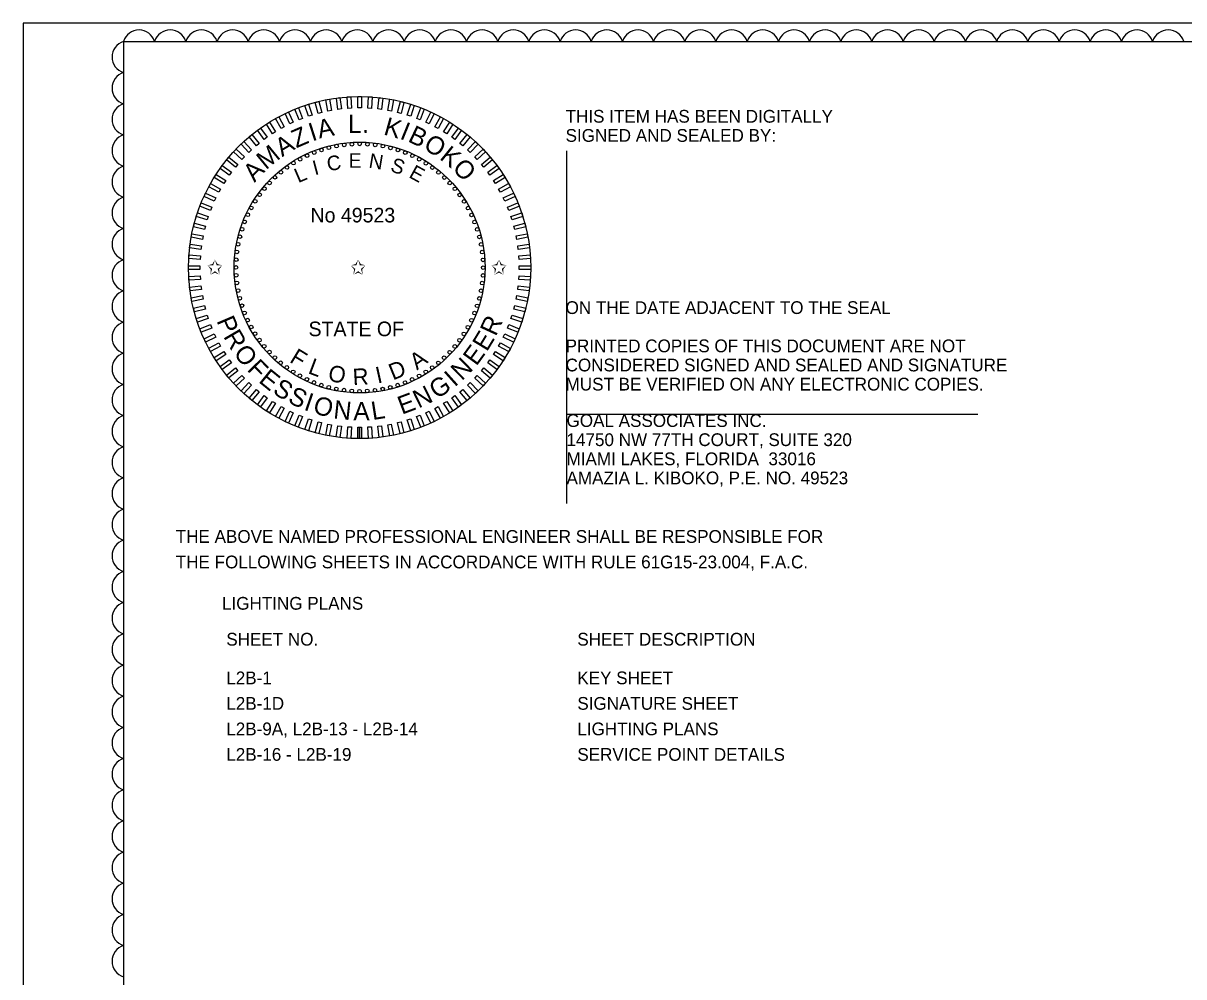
# Model space of a CAD drawing. Extents: x -816.9 to -790.1, y -2199.5 to -2184.5.
# Drawn here: x -811.34 to -804.97, y -2194.13 to -2188.9 of the extents above; entities that cross this region are included whole.
import ezdxf

# ---------------------------------------------------------------- set-up
doc = ezdxf.new("R2010")
doc.units = 0
for name, color, linetype in [('Cloud_dp', 7, 'Continuous'), ('Logo_dp', 7, 'Continuous'), ('NonPlottingEle_dp', 7, 'Continuous'), ('PlotBorder_dp', 7, 'Continuous'), ('ScratchEle_dp', 7, 'Continuous'), ('SheetBorder_dp', 7, 'Continuous'), ('TextMisc', 7, 'Continuous'), ('TextNotes', 7, 'Continuous')]:
    doc.layers.add(name, color=color, linetype=linetype)

msp = doc.modelspace()

# ---------------------------------------------------------------- linework, layer by layer
at = {"layer": 'Cloud_dp'}
for centre, start, end in [((-810.7002, -2189.0276), 17.5, 162.5), ((-810.5291, -2189.0276), 17.5, 162.5), ((-810.358, -2189.0276), 17.5, 162.5), ((-810.1868, -2189.0276), 17.5, 162.5), ((-810.0157, -2189.0276), 17.5, 162.5), ((-809.8446, -2189.0276), 17.5, 162.5), ((-809.6735, -2189.0276), 17.5, 162.5), ((-809.5024, -2189.0276), 17.5, 162.5), ((-809.3312, -2189.0276), 17.5, 162.5), ((-809.1601, -2189.0276), 17.5, 162.5), ((-808.989, -2189.0276), 17.5, 162.5), ((-808.8179, -2189.0276), 17.5, 162.5), ((-808.6467, -2189.0276), 17.5, 162.5), ((-808.4756, -2189.0276), 17.5, 162.5), ((-808.3045, -2189.0276), 17.5, 162.5), ((-808.1334, -2189.0276), 17.5, 162.5), ((-807.9622, -2189.0276), 17.5, 162.5), ((-807.7911, -2189.0276), 17.5, 162.5), ((-807.62, -2189.0276), 17.5, 162.5), ((-807.4489, -2189.0276), 17.5, 162.5), ((-807.2778, -2189.0276), 17.5, 162.5), ((-807.1066, -2189.0276), 17.5, 162.5), ((-806.9355, -2189.0276), 17.5, 162.5), ((-806.7644, -2189.0276), 17.5, 162.5), ((-806.5933, -2189.0276), 17.5, 162.5), ((-806.4221, -2189.0276), 17.5, 162.5), ((-806.251, -2189.0276), 17.5, 162.5), ((-806.0799, -2189.0276), 17.5, 162.5), ((-805.9088, -2189.0276), 17.5, 162.5), ((-805.7377, -2189.0276), 17.5, 162.5), ((-805.5665, -2189.0276), 17.5, 162.5), ((-805.3954, -2189.0276), 17.5, 162.5), ((-805.2243, -2189.0276), 17.5, 162.5), ((-805.0532, -2189.0276), 17.5, 162.5), ((-810.7588, -2189.0862), 107.5, 252.5), ((-810.7588, -2189.2573), 107.5, 252.5), ((-810.7588, -2189.4284), 107.5, 252.5), ((-810.7588, -2189.5996), 107.5, 252.5), ((-810.7588, -2189.7707), 107.5, 252.5), ((-810.7588, -2189.9418), 107.5, 252.5), ((-810.7588, -2190.1129), 107.5, 252.5), ((-810.7588, -2190.2841), 107.5, 252.5), ((-810.7588, -2190.4552), 107.5, 252.5), ((-810.7588, -2190.6263), 107.5, 252.5), ((-810.7588, -2190.7974), 107.5, 252.5), ((-810.7588, -2190.9685), 107.5, 252.5), ((-810.7588, -2191.1397), 107.5, 252.5), ((-810.7588, -2191.3108), 107.5, 252.5), ((-810.7588, -2191.4819), 107.5, 252.5), ((-810.7588, -2191.653), 107.5, 252.5), ((-810.7588, -2191.8242), 107.5, 252.5), ((-810.7588, -2191.9953), 107.5, 252.5), ((-810.7588, -2192.1664), 107.5, 252.5), ((-810.7588, -2192.3375), 107.5, 252.5), ((-810.7588, -2192.5087), 107.5, 252.5), ((-810.7588, -2192.6798), 107.5, 252.5), ((-810.7588, -2192.8509), 107.5, 252.5), ((-810.7588, -2193.022), 107.5, 252.5), ((-810.7588, -2193.1931), 107.5, 252.5), ((-810.7588, -2193.3643), 107.5, 252.5), ((-810.7588, -2193.5354), 107.5, 252.5), ((-810.7588, -2193.7065), 107.5, 252.5), ((-810.7588, -2193.8776), 107.5, 252.5), ((-810.7588, -2194.0488), 107.5, 252.5)]:
    msp.add_arc(centre, 0.0897, start, end, dxfattribs=at)
at = {"layer": 'Logo_dp'}
for p, q in [((-809.5, -2191.1804), (-809.5002, -2191.1179)), ((-809.49, -2191.1804), (-809.4902, -2191.1178)), ((-809.48, -2191.1804), (-809.4802, -2191.1178))]:
    msp.add_line(p, q, dxfattribs=at)
for points in [[(-809.5897, -2189.3711), (-809.6098, -2189.3737), (-809.6176, -2189.3116), (-809.5976, -2189.3091)], [(-809.5349, -2189.3666), (-809.555, -2189.3679), (-809.559, -2189.3055), (-809.5388, -2189.3042)], [(-809.4798, -2189.3655), (-809.5, -2189.3655), (-809.5, -2189.303), (-809.4798, -2189.303)], [(-809.4248, -2189.3679), (-809.445, -2189.3666), (-809.4411, -2189.3042), (-809.4209, -2189.3055)], [(-809.3701, -2189.3737), (-809.3901, -2189.3712), (-809.3823, -2189.3091), (-809.3623, -2189.3117)], [(-809.8031, -2189.4233), (-809.8219, -2189.4307), (-809.8449, -2189.3726), (-809.8261, -2189.3652)], [(-809.7511, -2189.4052), (-809.7703, -2189.4115), (-809.7896, -2189.352), (-809.7704, -2189.3458)], [(-809.698, -2189.3905), (-809.7176, -2189.3955), (-809.7332, -2189.335), (-809.7136, -2189.3299)], [(-809.6442, -2189.3791), (-809.664, -2189.3829), (-809.6758, -2189.3215), (-809.6559, -2189.3177)], [(-809.3158, -2189.3829), (-809.3357, -2189.3792), (-809.324, -2189.3177), (-809.3041, -2189.3215)], [(-809.2623, -2189.3956), (-809.2818, -2189.3905), (-809.2663, -2189.33), (-809.2467, -2189.335)], [(-809.2096, -2189.4115), (-809.2288, -2189.4053), (-809.2095, -2189.3458), (-809.1903, -2189.3521)], [(-809.158, -2189.4308), (-809.1768, -2189.4234), (-809.1538, -2189.3652), (-809.135, -2189.3727)], [(-809.9032, -2189.469), (-809.9209, -2189.4787), (-809.951, -2189.4239), (-809.9333, -2189.4142)], [(-809.8539, -2189.4446), (-809.8721, -2189.4532), (-809.8988, -2189.3966), (-809.8805, -2189.388)], [(-809.1077, -2189.4532), (-809.126, -2189.4446), (-809.0994, -2189.3881), (-809.0811, -2189.3967)], [(-809.059, -2189.4788), (-809.0767, -2189.4691), (-809.0466, -2189.4143), (-809.0289, -2189.424)], [(-809.9968, -2189.5268), (-810.0131, -2189.5387), (-810.0499, -2189.4881), (-810.0335, -2189.4763)], [(-809.9509, -2189.4964), (-809.968, -2189.5073), (-810.0015, -2189.4545), (-809.9844, -2189.4437)], [(-809.0119, -2189.5074), (-809.029, -2189.4965), (-808.9955, -2189.4438), (-808.9784, -2189.4546)], [(-808.9668, -2189.5388), (-808.9831, -2189.527), (-808.9464, -2189.4764), (-808.93, -2189.4883)], [(-810.0824, -2189.596), (-810.0971, -2189.6098), (-810.1399, -2189.5643), (-810.1252, -2189.5504)], [(-810.0407, -2189.5601), (-810.0562, -2189.573), (-810.0961, -2189.5248), (-810.0805, -2189.5119)], [(-808.9237, -2189.5731), (-808.9392, -2189.5602), (-808.8994, -2189.512), (-808.8838, -2189.5249)], [(-808.8828, -2189.61), (-808.8975, -2189.5961), (-808.8547, -2189.5505), (-808.84, -2189.5644)], [(-810.1217, -2189.6345), (-810.1356, -2189.6492), (-810.1812, -2189.6064), (-810.1673, -2189.5917)], [(-808.8443, -2189.6493), (-808.8582, -2189.6346), (-808.8126, -2189.5918), (-808.7988, -2189.6065)], [(-810.1929, -2189.7184), (-810.2048, -2189.7348), (-810.2553, -2189.698), (-810.2435, -2189.6817)], [(-810.1586, -2189.6753), (-810.1715, -2189.6909), (-810.2197, -2189.6511), (-810.2068, -2189.6355)], [(-808.8084, -2189.691), (-808.8213, -2189.6755), (-808.7731, -2189.6356), (-808.7602, -2189.6512)], [(-808.7752, -2189.7349), (-808.7871, -2189.7186), (-808.7365, -2189.6818), (-808.7246, -2189.6982)], [(-810.2243, -2189.7636), (-810.2352, -2189.7807), (-810.288, -2189.7472), (-810.2771, -2189.7301)], [(-808.7448, -2189.7808), (-808.7556, -2189.7638), (-808.7028, -2189.7303), (-808.692, -2189.7473)], [(-810.2529, -2189.8106), (-810.2626, -2189.8284), (-810.3174, -2189.7982), (-810.3077, -2189.7805)], [(-808.7173, -2189.8285), (-808.7271, -2189.8108), (-808.6723, -2189.7807), (-808.6625, -2189.7984)], [(-810.2785, -2189.8594), (-810.2871, -2189.8777), (-810.3436, -2189.8511), (-810.335, -2189.8328)], [(-808.6929, -2189.8779), (-808.7015, -2189.8596), (-808.6449, -2189.8329), (-808.6363, -2189.8512)], [(-810.3202, -2189.9612), (-810.3264, -2189.9805), (-810.3859, -2189.9611), (-810.3796, -2189.9419)], [(-810.3009, -2189.9097), (-810.3084, -2189.9285), (-810.3665, -2189.9054), (-810.359, -2189.8866)], [(-808.6716, -2189.9286), (-808.6791, -2189.9098), (-808.6209, -2189.8868), (-808.6135, -2189.9056)], [(-808.6536, -2189.9806), (-808.6598, -2189.9614), (-808.6004, -2189.9421), (-808.5941, -2189.9613)], [(-810.3361, -2190.0139), (-810.3412, -2190.0335), (-810.4017, -2190.0179), (-810.3967, -2189.9984)], [(-808.6388, -2190.0337), (-808.6439, -2190.0141), (-808.5833, -2189.9985), (-808.5783, -2190.0181)], [(-810.3488, -2190.0675), (-810.3526, -2190.0873), (-810.414, -2190.0756), (-810.4102, -2190.0558)], [(-808.6275, -2190.0875), (-808.6312, -2190.0677), (-808.5698, -2190.056), (-808.566, -2190.0758)], [(-810.358, -2190.1218), (-810.3605, -2190.1418), (-810.4226, -2190.134), (-810.42, -2190.1139)], [(-808.6195, -2190.142), (-808.622, -2190.1219), (-808.56, -2190.1141), (-808.5575, -2190.1342)], [(-810.3638, -2190.1765), (-810.3651, -2190.1967), (-810.4275, -2190.1927), (-810.4262, -2190.1726)], [(-808.6149, -2190.1968), (-808.6162, -2190.1767), (-808.5538, -2190.1727), (-808.5525, -2190.1929)], [(-810.3662, -2190.2315), (-810.3662, -2190.2517), (-810.4287, -2190.2517), (-810.4287, -2190.2315)], [(-808.6139, -2190.2519), (-808.6139, -2190.2317), (-808.5513, -2190.2317), (-808.5513, -2190.2519)], [(-810.3651, -2190.2865), (-810.3638, -2190.3067), (-810.4262, -2190.3106), (-810.4275, -2190.2904)], [(-808.6162, -2190.3069), (-808.615, -2190.2867), (-808.5526, -2190.2906), (-808.5538, -2190.3108)], [(-810.3606, -2190.3414), (-810.358, -2190.3614), (-810.4201, -2190.3693), (-810.4226, -2190.3492)], [(-808.622, -2190.3616), (-808.6195, -2190.3416), (-808.5575, -2190.3494), (-808.56, -2190.3695)], [(-810.3526, -2190.3958), (-810.3488, -2190.4157), (-810.4102, -2190.4274), (-810.414, -2190.4076)], [(-810.3412, -2190.4497), (-810.3362, -2190.4693), (-810.3967, -2190.4848), (-810.4018, -2190.4652)], [(-808.6439, -2190.4695), (-808.6389, -2190.4499), (-808.5783, -2190.4654), (-808.5834, -2190.485)], [(-808.6313, -2190.4159), (-808.6275, -2190.396), (-808.5661, -2190.4077), (-808.5699, -2190.4276)], [(-810.3265, -2190.5027), (-810.3202, -2190.522), (-810.3797, -2190.5413), (-810.3859, -2190.5221)], [(-808.6599, -2190.5221), (-808.6536, -2190.5029), (-808.5942, -2190.5222), (-808.6004, -2190.5415)], [(-810.3084, -2190.5547), (-810.301, -2190.5735), (-810.3591, -2190.5966), (-810.3666, -2190.5778)], [(-808.6791, -2190.5737), (-808.6717, -2190.5549), (-808.6136, -2190.5779), (-808.621, -2190.5967)], [(-810.2872, -2190.6055), (-810.2785, -2190.6238), (-810.3351, -2190.6504), (-810.3437, -2190.6321)], [(-808.7016, -2190.624), (-808.693, -2190.6057), (-808.6364, -2190.6323), (-808.645, -2190.6506)], [(-810.2627, -2190.6548), (-810.253, -2190.6726), (-810.3078, -2190.7027), (-810.3175, -2190.685)], [(-810.2353, -2190.7026), (-810.2244, -2190.7196), (-810.2772, -2190.7531), (-810.2881, -2190.7361)], [(-808.7557, -2190.7198), (-808.7449, -2190.7027), (-808.6921, -2190.7362), (-808.7029, -2190.7533)], [(-808.7271, -2190.6727), (-808.7174, -2190.655), (-808.6626, -2190.6851), (-808.6724, -2190.7028)], [(-810.2049, -2190.7484), (-810.193, -2190.7648), (-810.2436, -2190.8015), (-810.2554, -2190.7852)], [(-808.7872, -2190.7649), (-808.7753, -2190.7486), (-808.7247, -2190.7853), (-808.7366, -2190.8017)], [(-810.1716, -2190.7923), (-810.1587, -2190.8079), (-810.2069, -2190.8477), (-810.2198, -2190.8322)], [(-810.1357, -2190.834), (-810.1219, -2190.8488), (-810.1675, -2190.8916), (-810.1813, -2190.8768)], [(-808.8583, -2190.8489), (-808.8445, -2190.8342), (-808.7989, -2190.877), (-808.8127, -2190.8917)], [(-808.8214, -2190.808), (-808.8085, -2190.7925), (-808.7604, -2190.8323), (-808.7732, -2190.8479)], [(-810.0972, -2190.8734), (-810.0825, -2190.8872), (-810.1253, -2190.9328), (-810.14, -2190.919)], [(-808.8977, -2190.8874), (-808.8829, -2190.8735), (-808.8401, -2190.9191), (-808.8549, -2190.9329)], [(-810.0564, -2190.9103), (-810.0408, -2190.9232), (-810.0807, -2190.9713), (-810.0962, -2190.9585)], [(-810.0133, -2190.9445), (-809.9969, -2190.9564), (-810.0337, -2191.007), (-810.05, -2190.9951)], [(-808.9833, -2190.9565), (-808.9669, -2190.9446), (-808.9302, -2190.9952), (-808.9465, -2191.0071)], [(-808.9394, -2190.9233), (-808.9238, -2190.9104), (-808.884, -2190.9586), (-808.8995, -2190.9715)], [(-809.9681, -2190.976), (-809.951, -2190.9868), (-809.9845, -2191.0396), (-810.0016, -2191.0288)], [(-809.9211, -2191.0046), (-809.9034, -2191.0143), (-809.9335, -2191.0691), (-809.9512, -2191.0594)], [(-809.8723, -2191.0301), (-809.854, -2191.0387), (-809.8806, -2191.0953), (-809.8989, -2191.0867)], [(-809.1262, -2191.0388), (-809.1079, -2191.0302), (-809.0813, -2191.0868), (-809.0996, -2191.0954)], [(-809.0769, -2191.0144), (-809.0592, -2191.0047), (-809.029, -2191.0594), (-809.0467, -2191.0692)], [(-809.0292, -2190.9869), (-809.0121, -2190.9761), (-808.9786, -2191.0289), (-808.9957, -2191.0397)], [(-809.822, -2191.0526), (-809.8033, -2191.06), (-809.8263, -2191.1181), (-809.8451, -2191.1107)], [(-809.7705, -2191.0718), (-809.7513, -2191.0781), (-809.7706, -2191.1375), (-809.7898, -2191.1313)], [(-809.7178, -2191.0878), (-809.6982, -2191.0928), (-809.7138, -2191.1534), (-809.7333, -2191.1484)], [(-809.282, -2191.0929), (-809.2624, -2191.0878), (-809.2469, -2191.1484), (-809.2665, -2191.1534)], [(-809.229, -2191.0781), (-809.2097, -2191.0719), (-809.1904, -2191.1313), (-809.2097, -2191.1376)], [(-809.177, -2191.0601), (-809.1582, -2191.0526), (-809.1352, -2191.1108), (-809.154, -2191.1182)], [(-809.6642, -2191.1004), (-809.6444, -2191.1042), (-809.6561, -2191.1656), (-809.6759, -2191.1618)], [(-809.61, -2191.1097), (-809.5899, -2191.1122), (-809.5977, -2191.1742), (-809.6178, -2191.1717)], [(-809.5552, -2191.1155), (-809.535, -2191.1168), (-809.539, -2191.1792), (-809.5591, -2191.1779)], [(-809.5002, -2191.1179), (-809.48, -2191.1179), (-809.48, -2191.1804), (-809.5002, -2191.1804)], [(-809.4452, -2191.1168), (-809.425, -2191.1155), (-809.4211, -2191.1779), (-809.4413, -2191.1792)], [(-809.3903, -2191.1122), (-809.3703, -2191.1097), (-809.3624, -2191.1717), (-809.3825, -2191.1743)], [(-809.3359, -2191.1043), (-809.316, -2191.1005), (-809.3043, -2191.1619), (-809.3241, -2191.1657)]]:
    msp.add_lwpolyline(points, close=True, dxfattribs=at)
for centre in [(-809.6166, -2189.5752), (-809.5745, -2189.5686), (-809.5321, -2189.5646), (-809.4895, -2189.5633), (-809.4469, -2189.5647), (-809.4044, -2189.5687), (-809.3624, -2189.5755), (-809.7783, -2189.6277), (-809.7392, -2189.6108), (-809.6991, -2189.5964), (-809.6582, -2189.5845), (-809.3208, -2189.5848), (-809.2799, -2189.5967), (-809.2398, -2189.6112), (-809.2007, -2189.6281), (-809.8883, -2189.6926), (-809.853, -2189.6686), (-809.8163, -2189.647), (-809.1627, -2189.6475), (-809.1261, -2189.6692), (-809.0908, -2189.6932), (-809.954, -2189.7468), (-809.922, -2189.7186), (-809.0572, -2189.7194), (-809.0252, -2189.7476), (-810.0123, -2189.8088), (-809.9841, -2189.7769), (-808.9951, -2189.7777), (-808.967, -2189.8097), (-810.0625, -2189.8777), (-810.0385, -2189.8425), (-808.9409, -2189.8434), (-808.917, -2189.8787), (-810.1036, -2189.9523), (-810.0842, -2189.9144), (-808.8953, -2189.9154), (-808.876, -2189.9534), (-810.1205, -2189.9914), (-808.8591, -2189.9925), (-810.1469, -2190.0724), (-810.135, -2190.0315), (-808.8447, -2190.0326), (-808.8328, -2190.0735), (-810.1563, -2190.114), (-808.8236, -2190.1151), (-810.167, -2190.1985), (-810.163, -2190.1561), (-808.8169, -2190.1572), (-808.813, -2190.1997), (-810.1684, -2190.2411), (-808.8117, -2190.2422), (-810.1671, -2190.2837), (-810.1631, -2190.3261), (-808.8171, -2190.3273), (-808.813, -2190.2848), (-810.1565, -2190.3682), (-808.8238, -2190.3693), (-810.1472, -2190.4098), (-810.1354, -2190.4508), (-808.845, -2190.4518), (-808.8331, -2190.4109), (-810.121, -2190.4909), (-810.1041, -2190.53), (-808.8595, -2190.4919), (-810.0847, -2190.568), (-808.8959, -2190.569), (-808.8765, -2190.531), (-810.0631, -2190.6047), (-810.0392, -2190.64), (-808.9416, -2190.6409), (-808.9176, -2190.6056), (-810.0131, -2190.6736), (-809.9849, -2190.7056), (-808.9959, -2190.7065), (-808.9677, -2190.6745), (-809.9548, -2190.7358), (-809.9229, -2190.764), (-809.0581, -2190.7647), (-809.0261, -2190.7366), (-809.8892, -2190.7902), (-809.854, -2190.8141), (-809.8173, -2190.8359), (-809.1637, -2190.8364), (-809.127, -2190.8147), (-809.0918, -2190.7908), (-809.7794, -2190.8552), (-809.7403, -2190.8722), (-809.7002, -2190.8867), (-809.6593, -2190.8986), (-809.6177, -2190.9079), (-809.3635, -2190.9081), (-809.3219, -2190.8989), (-809.2809, -2190.887), (-809.2408, -2190.8726), (-809.2017, -2190.8557), (-809.5756, -2190.9146), (-809.5332, -2190.9187), (-809.49, -2190.9201), (-809.448, -2190.9187), (-809.4056, -2190.9148)]:
    msp.add_circle(centre, 0.01, dxfattribs=at)
at = {"layer": 'NonPlottingEle_dp'}
for radius in [0.9387, 0.6884]:
    msp.add_circle((-809.49, -2190.2417), radius, dxfattribs=at)
at = {"layer": 'PlotBorder_dp'}
msp.add_lwpolyline([(-811.3358, -2199.5006), (-794.8358, -2199.5006), (-794.8358, -2188.9006), (-811.3358, -2188.9006)], close=True, dxfattribs=at)
at = {"layer": 'ScratchEle_dp'}
for p, q in [((-808.3546, -2189.6017), (-808.3546, -2191.5365)), ((-808.3546, -2191.0465), (-806.0979, -2191.0465))]:
    msp.add_line(p, q, dxfattribs=at)
at = {"layer": 'SheetBorder_dp'}
for q in [(-810.7858, -2199.4006), (-795.3858, -2189.0006)]:
    msp.add_line((-810.7858, -2189.0006), q, dxfattribs=at)

# ---------------------------------------------------------------- texts
at = {"layer": 'Logo_dp'}
for s, rotation, p in [('C', 8.98261, (-809.6632, -2189.7131)), ('E', 359.96623, (-809.5504, -2189.6942)), ('N', 350.64643, (-809.4434, -2189.6927)), ('I', 14.81888, (-809.7359, -2189.7358)), ('S', 341.03996, (-809.3261, -2189.7116)), ('E', 331.16864, (-809.2245, -2189.7442)), ('L', 23.30524, (-809.8266, -2189.7788))]:
    msp.add_text(s, height=0.0801, rotation=rotation, dxfattribs=at).set_placement(p)
for p in [(-810.3261, -2190.2797), (-809.5404, -2190.2797), (-808.7675, -2190.2797)]:
    msp.add_text('✩', height=0.0801, dxfattribs=at).set_placement(p)
at = {"layer": 'TextMisc'}
for s, height, rotation, p in [('A', 0.1001, 11.91844, (-809.7111, -2189.5338)), ('L', 0.1001, 359.96623, (-809.5537, -2189.5034)), ('K', 0.1001, 344.27273, (-809.3628, -2189.5106)), ('Z', 0.1001, 23.30524, (-809.8374, -2189.5875)), ('I', 0.1001, 17.68363, (-809.7505, -2189.5498)), ('.', 0.1001, 353.78581, (-809.4769, -2189.5005)), ('I', 0.1001, 337.77772, (-809.2741, -2189.5325)), ('B', 0.1001, 334.48695, (-809.23, -2189.5478)), ('A', 0.1001, 31.46601, (-809.9149, -2189.6362)), ('O', 0.1001, 327.82385, (-809.1453, -2189.5865)), ('M', 0.1001, 39.30005, (-810.0041, -2189.7084)), ('K', 0.1001, 321.0594, (-809.0556, -2189.6437)), ('A', 0.1001, 46.80938, (-810.0664, -2189.777)), ('O', 0.1001, 314.20329, (-808.9858, -2189.7014)), ('P', 0.1002, 293.19548, (-810.2767, -2190.5336)), ('R', 0.1002, 65.28865, (-808.7427, -2190.6231)), ('R', 0.1002, 300.25949, (-810.2398, -2190.6197)), ('E', 0.1002, 58.61694, (-808.7919, -2190.7072)), ('O', 0.1002, 307.26617, (-810.1856, -2190.7116)), ('F', 0.0902, 328.53399, (-809.879, -2190.7577)), ('A', 0.0902, 35.54629, (-809.1752, -2190.807)), ('E', 0.1002, 53.99864, (-808.8492, -2190.786)), ('F', 0.1002, 314.20329, (-810.1121, -2190.8042)), ('L', 0.0902, 339.48752, (-809.7776, -2190.8207)), ('D', 0.0902, 22.22228, (-809.3071, -2190.8616)), ('N', 0.1002, 44.34211, (-808.9294, -2190.866)), ('E', 0.1002, 321.0594, (-810.0487, -2190.8679)), ('O', 0.0902, 348.08156, (-809.668, -2190.8614)), ('R', 0.0902, 3.10738, (-809.5257, -2190.8876)), ('I', 0.0902, 12.52485, (-809.3913, -2190.8785)), ('I', 0.1002, 41.83906, (-808.9688, -2190.9003)), ('S', 0.1002, 327.82385, (-809.9723, -2190.9285)), ('S', 0.1002, 334.48695, (-809.8891, -2190.98)), ('N', 0.1002, 26.0618, (-809.1664, -2191.0166)), ('G', 0.1002, 34.11362, (-809.0651, -2190.9664)), ('I', 0.1002, 341.03996, (-809.8004, -2191.0213)), ('O', 0.1002, 344.27273, (-809.7512, -2191.0389)), ('E', 0.1002, 20.51248, (-809.2581, -2191.0499)), ('N', 0.1002, 353.78581, (-809.6367, -2191.0689)), ('A', 0.1002, 359.96623, (-809.5242, -2191.0799)), ('L', 0.1002, 8.98261, (-809.4185, -2191.079))]:
    msp.add_text(s, height=height, rotation=rotation, dxfattribs=at).set_placement(p)
for s, height, p in [('THIS ITEM HAS BEEN DIGITALLY', 0.07, (-808.3596, -2189.4466)), ('SIGNED AND SEALED BY:', 0.07, (-808.3596, -2189.5516)), ('No 49523', 0.0801, (-809.7593, -2189.9941)), ('ON THE DATE ADJACENT TO THE SEAL', 0.07, (-808.3596, -2190.4966)), ('STATE OF', 0.0801, (-809.7701, -2190.6184)), ('PRINTED COPIES OF THIS DOCUMENT ARE NOT ', 0.07, (-808.3596, -2190.7066)), ('CONSIDERED SIGNED AND SEALED AND SIGNATURE ', 0.07, (-808.3596, -2190.8116)), ('MUST BE VERIFIED ON ANY ELECTRONIC COPIES.', 0.07, (-808.3596, -2190.9166)), ('GOAL ASSOCIATES INC.', 0.07, (-808.3546, -2191.1165)), ('14750 NW 77TH COURT, SUITE 320', 0.07, (-808.3546, -2191.2215)), ('MIAMI LAKES, FLORIDA  33016', 0.07, (-808.3546, -2191.3265)), ('AMAZIA L. KIBOKO, P.E. NO. 49523', 0.07, (-808.3546, -2191.4315)), ('THE ABOVE NAMED PROFESSIONAL ENGINEER SHALL BE RESPONSIBLE FOR ', 0.07, (-810.4987, -2191.7526)), ('THE FOLLOWING SHEETS IN ACCORDANCE WITH RULE 61G15-23.004, F.A.C.', 0.07, (-810.4987, -2191.8926)), ('LIGHTING PLANS', 0.07, (-810.245, -2192.1196))]:
    msp.add_text(s, height=height, dxfattribs=at).set_placement(p)
at = {"layer": 'TextNotes'}
for s, p in [('SHEET NO.', (-810.2215, -2192.3166)), ('SHEET DESCRIPTION', (-808.2953, -2192.3166)), ('L2B-1', (-810.2215, -2192.5288)), ('KEY SHEET', (-808.2953, -2192.5288)), ('L2B-1D', (-810.2215, -2192.6688)), ('SIGNATURE SHEET', (-808.2953, -2192.6688)), ('L2B-9A, L2B-13 - L2B-14', (-810.2215, -2192.8088)), ('LIGHTING PLANS', (-808.2953, -2192.8088)), ('L2B-16 - L2B-19', (-810.2215, -2192.9488)), ('SERVICE POINT DETAILS', (-808.2953, -2192.9488))]:
    msp.add_text(s, height=0.07, dxfattribs=at).set_placement(p)

doc.saveas('drawing.dxf')
